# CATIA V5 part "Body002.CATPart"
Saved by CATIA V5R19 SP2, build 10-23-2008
Part number: Body002
Definition: design
Nomenclature: Body002
Source: Unknown
Bounding box of the stored display mesh (mm): x -56.25 to 47.75, y -35.58 to 36.42, z 0 to 23
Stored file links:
  Z:\fausse table rondelle-20220905T211342Z-001\fausse table rondelle\Body002.CATPart
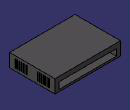
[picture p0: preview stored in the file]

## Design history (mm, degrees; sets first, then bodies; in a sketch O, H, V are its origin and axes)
AxisSystem1: origin (0, 0, 0), X (1, 0, 0), Y (0, 1, 0), Z (0, 0, 1)
Body1 "MANIFOLD_SOLID_BREP #6666" (main body)
  Solid1: solid without history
